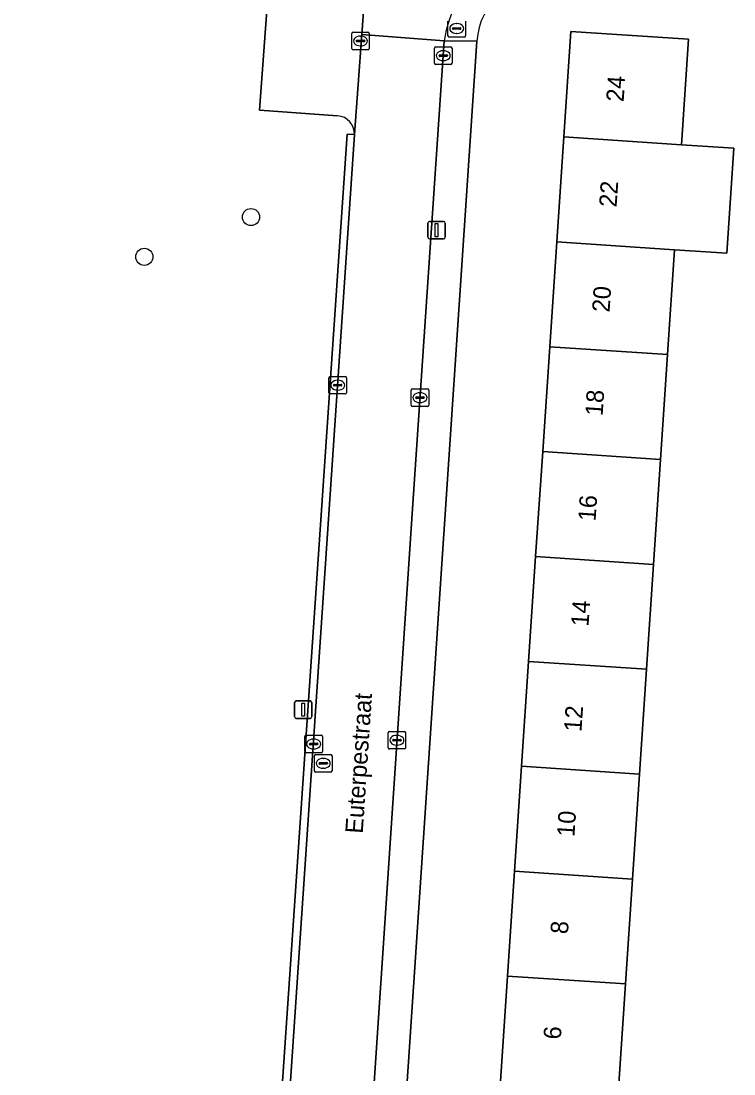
# Model space of a CAD drawing. Extents: x 161848 to 162726, y 385382 to 386521.
# Drawn here: x 161955.5 to 161996.3, y 386169.4 to 386229.5 of the extents above; entities that cross this region are included whole.
import ezdxf

# ---------------------------------------------------------------- set-up
doc = ezdxf.new("R2010")
doc.units = 0
for name, color, linetype in [('IMGEO_Boom', 7, 'Continuous'), ('IMGEO_Brandkraan', 7, 'Continuous'), ('IMGEO_Erf', 7, 'Continuous'), ('IMGEO_Groenvoorziening', 7, 'Continuous'), ('IMGEO_Kolk', 7, 'Continuous'), ('IMGEO_Lichtmast', 7, 'Continuous'), ('IMGEO_Openbare_ruimte_label', 7, 'Continuous'), ('IMGEO_Pand', 7, 'Continuous'), ('IMGEO_Pand_nummerreeks', 7, 'Continuous'), ('IMGEO_Parkeervlak_open', 7, 'Continuous'), ('IMGEO_Rijbaan_lokaal_open', 7, 'Continuous'), ('IMGEO_Rioolput', 7, 'Continuous'), ('IMGEO_Verkeerseiland_open', 7, 'Continuous'), ('IMGEO_Voetpad_open', 7, 'Continuous')]:
    doc.layers.add(name, color=color, linetype=linetype)

msp = doc.modelspace()

# ---------------------------------------------------------------- linework, layer by layer
at = {"layer": 'IMGEO_Boom'}
for centre in [(161968.672, 386218.342), (161962.577, 386216.067)]:
    msp.add_circle(centre, 0.489, dxfattribs=at)
at = {"layer": 'IMGEO_Brandkraan'}
for p, q in [((161979.933, 386228.689), (161979.933, 386229.541)), ((161980.421, 386229.395), (161980.446, 386229.395)), ((161980.934, 386229.541), (161980.934, 386228.689)), ((161980.86, 386228.615), (161980.008, 386228.615)), ((161980.192, 386229.109), (161980.192, 386229.121)), ((161980.63, 386229.072), (161980.232, 386229.072)), ((161980.235, 386229.158), (161980.633, 386229.158)), ((161980.444, 386228.835), (161980.419, 386228.835)), ((161980.676, 386229.121), (161980.676, 386229.109))]:
    msp.add_line(p, q, dxfattribs=at)
for points in [[(161979.933, 386228.689), (161979.933, 386229.541)], [(161980.934, 386229.541), (161980.934, 386228.689)], [(161980.86, 386228.615), (161980.008, 386228.615)]]:
    msp.add_lwpolyline(points, dxfattribs=at)
for centre, radius, start, end in [((161980.01, 386228.691), 0.0765, 181.55205, 268.44795), ((161980.01, 386228.691), 0.0765, 181.55205, 268.44795), ((161980.232, 386229.118), 0.0403, 85.87752, 175.75265), ((161980.229, 386229.108), 0.0366, 178.93798, 274.71019), ((161980.633, 386229.115), 0.043, 264.86636, 352.45326), ((161980.637, 386229.12), 0.0386, 1.73085, 96.63898), ((161980.858, 386228.691), 0.0765, 271.55205, 358.44795), ((161980.858, 386228.691), 0.0765, 271.55205, 358.44795)]:
    msp.add_arc(centre, radius, start, end, dxfattribs=at)
for centre, major_axis, ratio, start_param, end_param in [((161980.42, 386229.115), (-0.387, 0.002), 0.722429, 4.712389, 7.853982), ((161980.445, 386229.115), (-0.39, 0.002), 0.717154, 1.570796, 4.712389)]:
    msp.add_ellipse(centre, major_axis=major_axis, ratio=ratio, start_param=start_param, end_param=end_param, dxfattribs=at)
at = {"layer": 'IMGEO_Erf'}
for points in [[(161982.937, 386168.979), (161983.339, 386174.973), (161983.74, 386180.967), (161984.141, 386186.961), (161984.543, 386192.955), (161984.944, 386198.948), (161985.346, 386204.941), (161985.747, 386210.936), (161986.149, 386216.93), (161986.55, 386222.924), (161986.954, 386228.951), (161993.689, 386228.5), (161993.285, 386222.473), (161996.278, 386222.273), (161995.877, 386216.278), (161992.884, 386216.479), (161992.482, 386210.485), (161992.081, 386204.491), (161991.679, 386198.498), (161991.278, 386192.504), (161990.876, 386186.51), (161990.475, 386180.516), (161990.074, 386174.523), (161989.672, 386168.529)], [(161981.585, 386228.399), (161976.646, 386154.728)]]:
    msp.add_lwpolyline(points, dxfattribs=at)
msp.add_arc((161985.479, 386228.136), 3.903, 86.19164, 176.13527, dxfattribs=at)
at = {"layer": 'IMGEO_Groenvoorziening'}
for points in [[(161973.622, 386224.131), (161969.156, 386224.443), (161970.081, 386236.899), (161970.003, 386237.069), (161959.96, 386237.714), (161960.789, 386250), (161961.577, 386261.676), (161960.683, 386261.649), (161960.872, 386264.321), (161951.691, 386264.934), (161951.406, 386249.482), (161944.516, 386146.672), (161954.397, 386146.32), (161963.923, 386145.981), (161964.898, 386160.997), (161969.377, 386160.715)], [(161970.434, 386161.661), (161969.985, 386161.69), (161974.167, 386223.078)], [(161974.167, 386223.078), (161974.584, 386223.052)]]:
    msp.add_lwpolyline(points, dxfattribs=at)
msp.add_arc((161973.548, 386223.097), 1.037, 357.50919, 85.92905, dxfattribs=at)
at = {"layer": 'IMGEO_Kolk'}
for p, q in [((161974.433, 386227.979), (161974.433, 386228.831)), ((161974.508, 386228.905), (161975.36, 386228.905)), ((161974.921, 386228.685), (161974.946, 386228.685)), ((161975.434, 386228.831), (161975.434, 386227.979)), ((161974.692, 386228.399), (161974.692, 386228.411)), ((161975.13, 386228.362), (161974.732, 386228.362)), ((161974.735, 386228.448), (161975.133, 386228.448)), ((161974.944, 386228.125), (161974.919, 386228.125)), ((161975.176, 386228.411), (161975.176, 386228.399)), ((161979.239, 386228.062), (161980.091, 386228.062)), ((161975.36, 386227.905), (161974.508, 386227.905)), ((161979.164, 386227.136), (161979.164, 386227.988)), ((161979.423, 386227.556), (161979.423, 386227.568)), ((161979.861, 386227.519), (161979.463, 386227.519)), ((161979.466, 386227.605), (161979.864, 386227.605)), ((161979.652, 386227.842), (161979.677, 386227.842)), ((161979.907, 386227.568), (161979.907, 386227.556)), ((161980.165, 386227.988), (161980.165, 386227.136)), ((161980.091, 386227.062), (161979.239, 386227.062)), ((161979.675, 386227.282), (161979.65, 386227.282)), ((161973.129, 386208.308), (161973.129, 386209.16)), ((161973.204, 386209.234), (161974.056, 386209.234)), ((161973.388, 386208.728), (161973.388, 386208.74)), ((161973.431, 386208.777), (161973.829, 386208.777)), ((161973.617, 386209.014), (161973.642, 386209.014)), ((161973.872, 386208.74), (161973.872, 386208.728)), ((161974.13, 386209.16), (161974.13, 386208.308)), ((161974.056, 386208.234), (161973.204, 386208.234)), ((161973.826, 386208.691), (161973.428, 386208.691)), ((161973.64, 386208.454), (161973.615, 386208.454)), ((161977.832, 386207.599), (161977.832, 386208.451)), ((161977.907, 386208.525), (161978.759, 386208.525)), ((161978.32, 386208.305), (161978.345, 386208.305)), ((161978.833, 386208.451), (161978.833, 386207.599)), ((161978.091, 386208.019), (161978.091, 386208.031)), ((161978.529, 386207.982), (161978.131, 386207.982)), ((161978.134, 386208.068), (161978.532, 386208.068)), ((161978.343, 386207.745), (161978.318, 386207.745)), ((161978.575, 386208.031), (161978.575, 386208.019)), ((161978.759, 386207.525), (161977.907, 386207.525)), ((161976.588, 386188.949), (161977.44, 386188.949)), ((161971.755, 386187.807), (161971.755, 386188.659)), ((161971.83, 386188.733), (161972.682, 386188.733)), ((161972.243, 386188.513), (161972.268, 386188.513)), ((161972.756, 386188.659), (161972.756, 386187.807)), ((161976.513, 386188.023), (161976.513, 386188.875)), ((161976.772, 386188.443), (161976.772, 386188.455)), ((161977.21, 386188.406), (161976.812, 386188.406)), ((161976.815, 386188.492), (161977.213, 386188.492)), ((161977.001, 386188.729), (161977.026, 386188.729)), ((161977.256, 386188.455), (161977.256, 386188.443)), ((161977.514, 386188.875), (161977.514, 386188.023)), ((161972.682, 386187.733), (161971.83, 386187.733)), ((161972.014, 386188.227), (161972.014, 386188.239)), ((161972.452, 386188.19), (161972.054, 386188.19)), ((161972.057, 386188.276), (161972.455, 386188.276)), ((161972.266, 386187.953), (161972.241, 386187.953)), ((161972.498, 386188.239), (161972.498, 386188.227)), ((161977.44, 386187.949), (161976.588, 386187.949)), ((161977.024, 386188.169), (161976.999, 386188.169))]:
    msp.add_line(p, q, dxfattribs=at)
for points in [[(161974.433, 386227.979), (161974.433, 386228.831)], [(161974.508, 386228.905), (161975.36, 386228.905)], [(161975.434, 386228.831), (161975.434, 386227.979)], [(161979.239, 386228.062), (161980.091, 386228.062)], [(161975.36, 386227.905), (161974.508, 386227.905)], [(161979.164, 386227.136), (161979.164, 386227.988)], [(161980.165, 386227.988), (161980.165, 386227.136)], [(161980.091, 386227.062), (161979.239, 386227.062)], [(161973.129, 386208.308), (161973.129, 386209.16)], [(161973.204, 386209.234), (161974.056, 386209.234)], [(161974.13, 386209.16), (161974.13, 386208.308)], [(161974.056, 386208.234), (161973.204, 386208.234)], [(161977.832, 386207.599), (161977.832, 386208.451)], [(161977.907, 386208.525), (161978.759, 386208.525)], [(161978.833, 386208.451), (161978.833, 386207.599)], [(161978.759, 386207.525), (161977.907, 386207.525)], [(161976.588, 386188.949), (161977.44, 386188.949)], [(161971.755, 386187.807), (161971.755, 386188.659)], [(161971.83, 386188.733), (161972.682, 386188.733)], [(161972.756, 386188.659), (161972.756, 386187.807)], [(161976.513, 386188.023), (161976.513, 386188.875)], [(161977.514, 386188.875), (161977.514, 386188.023)], [(161972.682, 386187.733), (161971.83, 386187.733)], [(161977.44, 386187.949), (161976.588, 386187.949)]]:
    msp.add_lwpolyline(points, dxfattribs=at)
for centre, radius, start, end in [((161974.51, 386228.829), 0.0765, 91.55205, 178.44795), ((161974.51, 386228.829), 0.0765, 91.55205, 178.44795), ((161975.358, 386228.829), 0.0765, 1.55205, 88.44795), ((161975.358, 386228.829), 0.0765, 1.55205, 88.44795), ((161974.732, 386228.408), 0.0403, 85.87752, 175.75265), ((161974.729, 386228.398), 0.0366, 178.93798, 274.71019), ((161975.133, 386228.405), 0.043, 264.86636, 352.45326), ((161975.137, 386228.41), 0.0386, 1.73085, 96.63898), ((161979.241, 386227.986), 0.0765, 91.55205, 178.44795), ((161979.241, 386227.986), 0.0765, 91.55205, 178.44795), ((161980.089, 386227.986), 0.0765, 1.55205, 88.44795), ((161980.089, 386227.986), 0.0765, 1.55205, 88.44795), ((161974.51, 386227.981), 0.0765, 181.55205, 268.44795), ((161974.51, 386227.981), 0.0765, 181.55205, 268.44795), ((161975.358, 386227.981), 0.0765, 271.55205, 358.44795), ((161975.358, 386227.981), 0.0765, 271.55205, 358.44795), ((161979.463, 386227.565), 0.0403, 85.87752, 175.75265), ((161979.46, 386227.555), 0.0366, 178.93798, 274.71019), ((161979.864, 386227.562), 0.043, 264.86636, 352.45326), ((161979.868, 386227.567), 0.0386, 1.73085, 96.63898), ((161979.241, 386227.138), 0.0765, 181.55205, 268.44795), ((161979.241, 386227.138), 0.0765, 181.55205, 268.44795), ((161980.089, 386227.138), 0.0765, 271.55205, 358.44795), ((161980.089, 386227.138), 0.0765, 271.55205, 358.44795), ((161973.206, 386209.158), 0.0765, 91.55205, 178.44795), ((161973.206, 386209.158), 0.0765, 91.55205, 178.44795), ((161973.428, 386208.737), 0.0403, 85.87752, 175.75265), ((161973.833, 386208.739), 0.0386, 1.73085, 96.63898), ((161974.054, 386209.158), 0.0765, 1.55205, 88.44795), ((161974.054, 386209.158), 0.0765, 1.55205, 88.44795), ((161973.206, 386208.31), 0.0765, 181.55205, 268.44795), ((161973.206, 386208.31), 0.0765, 181.55205, 268.44795), ((161973.425, 386208.727), 0.0366, 178.93798, 274.71019), ((161973.829, 386208.734), 0.043, 264.86636, 352.45326), ((161974.054, 386208.31), 0.0765, 271.55205, 358.44795), ((161974.054, 386208.31), 0.0765, 271.55205, 358.44795), ((161977.909, 386208.449), 0.0765, 91.55205, 178.44795), ((161977.909, 386208.449), 0.0765, 91.55205, 178.44795), ((161978.757, 386208.449), 0.0765, 1.55205, 88.44795), ((161978.757, 386208.449), 0.0765, 1.55205, 88.44795), ((161977.909, 386207.601), 0.0765, 181.55205, 268.44795), ((161977.909, 386207.601), 0.0765, 181.55205, 268.44795), ((161978.131, 386208.028), 0.0403, 85.87752, 175.75265), ((161978.128, 386208.018), 0.0366, 178.93798, 274.71019), ((161978.532, 386208.025), 0.043, 264.86636, 352.45326), ((161978.536, 386208.03), 0.0386, 1.73085, 96.63898), ((161978.757, 386207.601), 0.0765, 271.55205, 358.44795), ((161978.757, 386207.601), 0.0765, 271.55205, 358.44795), ((161976.59, 386188.873), 0.0765, 91.55205, 178.44795), ((161976.59, 386188.873), 0.0765, 91.55205, 178.44795), ((161977.438, 386188.873), 0.0765, 1.55205, 88.44795), ((161977.438, 386188.873), 0.0765, 1.55205, 88.44795), ((161971.832, 386188.657), 0.0765, 91.55205, 178.44795), ((161971.832, 386188.657), 0.0765, 91.55205, 178.44795), ((161972.68, 386188.657), 0.0765, 1.55205, 88.44795), ((161972.68, 386188.657), 0.0765, 1.55205, 88.44795), ((161976.812, 386188.452), 0.0403, 85.87752, 175.75265), ((161976.809, 386188.442), 0.0366, 178.93798, 274.71019), ((161977.213, 386188.449), 0.043, 264.86636, 352.45326), ((161977.217, 386188.454), 0.0386, 1.73085, 96.63898), ((161971.832, 386187.809), 0.0765, 181.55205, 268.44795), ((161971.832, 386187.809), 0.0765, 181.55205, 268.44795), ((161972.054, 386188.236), 0.0403, 85.87752, 175.75265), ((161972.051, 386188.226), 0.0366, 178.93798, 274.71019), ((161972.455, 386188.233), 0.043, 264.86636, 352.45326), ((161972.459, 386188.238), 0.0386, 1.73085, 96.63898), ((161972.68, 386187.809), 0.0765, 271.55205, 358.44795), ((161972.68, 386187.809), 0.0765, 271.55205, 358.44795), ((161976.59, 386188.025), 0.0765, 181.55205, 268.44795), ((161976.59, 386188.025), 0.0765, 181.55205, 268.44795), ((161977.438, 386188.025), 0.0765, 271.55205, 358.44795), ((161977.438, 386188.025), 0.0765, 271.55205, 358.44795)]:
    msp.add_arc(centre, radius, start, end, dxfattribs=at)
for centre, major_axis, ratio, start_param, end_param in [((161974.92, 386228.405), (-0.387, 0.002), 0.722429, 4.712389, 7.853982), ((161974.945, 386228.405), (-0.39, 0.002), 0.717154, 1.570796, 4.712389), ((161979.651, 386227.562), (-0.387, 0.002), 0.722429, 4.712389, 7.853982), ((161979.676, 386227.562), (-0.39, 0.002), 0.717154, 1.570796, 4.712389), ((161973.616, 386208.734), (-0.387, 0.002), 0.722429, 4.712389, 7.853982), ((161973.641, 386208.734), (-0.39, 0.002), 0.717154, 1.570796, 4.712389), ((161978.319, 386208.025), (-0.387, 0.002), 0.722429, 4.712389, 7.853982), ((161978.344, 386208.025), (-0.39, 0.002), 0.717154, 1.570796, 4.712389), ((161972.242, 386188.233), (-0.387, 0.002), 0.722429, 4.712389, 7.853982), ((161972.267, 386188.233), (-0.39, 0.002), 0.717154, 1.570796, 4.712389), ((161977, 386188.449), (-0.387, 0.002), 0.722429, 4.712389, 7.853982), ((161977.025, 386188.449), (-0.39, 0.002), 0.717154, 1.570796, 4.712389)]:
    msp.add_ellipse(centre, major_axis=major_axis, ratio=ratio, start_param=start_param, end_param=end_param, dxfattribs=at)
at = {"layer": 'IMGEO_Lichtmast'}
for p, q in [((161978.783, 386217.195), (161978.783, 386217.995)), ((161978.783, 386217.995), (161978.783, 386217.195)), ((161978.883, 386218.095), (161979.673, 386218.095)), ((161979.673, 386218.095), (161978.883, 386218.095)), ((161979.773, 386217.995), (161979.773, 386217.195)), ((161979.773, 386217.195), (161979.773, 386217.995)), ((161979.673, 386217.095), (161978.883, 386217.095)), ((161978.883, 386217.095), (161979.673, 386217.095)), ((161971.261, 386190.698), (161972.051, 386190.698)), ((161972.051, 386190.698), (161971.261, 386190.698)), ((161971.161, 386189.798), (161971.161, 386190.598)), ((161971.161, 386190.598), (161971.161, 386189.798)), ((161972.151, 386190.598), (161972.151, 386189.798)), ((161972.151, 386189.798), (161972.151, 386190.598)), ((161972.051, 386189.698), (161971.261, 386189.698)), ((161971.261, 386189.698), (161972.051, 386189.698))]:
    msp.add_line(p, q, dxfattribs=at)
for points in [[(161979.203, 386217.97), (161979.353, 386217.97), (161979.353, 386217.22), (161979.203, 386217.22), (161979.203, 386217.97)], [(161971.581, 386190.573), (161971.731, 386190.573), (161971.731, 386189.823), (161971.581, 386189.823), (161971.581, 386190.573)]]:
    msp.add_lwpolyline(points, dxfattribs=at)
for centre, start, end in [((161978.883, 386217.995), 90, 180), ((161978.883, 386217.995), 90, 180), ((161979.673, 386217.995), 0, 90), ((161979.673, 386217.995), 360, 90), ((161978.883, 386217.195), 180, 270), ((161978.883, 386217.195), 180, 270), ((161979.673, 386217.195), 270, 0), ((161979.673, 386217.195), 270, 0), ((161971.261, 386190.598), 90, 180), ((161971.261, 386190.598), 90, 180), ((161972.051, 386190.598), 0, 90), ((161972.051, 386190.598), 360, 90), ((161971.261, 386189.798), 180, 270), ((161971.261, 386189.798), 180, 270), ((161972.051, 386189.798), 270, 0), ((161972.051, 386189.798), 270, 0)]:
    msp.add_arc(centre, 0.1, start, end, dxfattribs=at)
at = {"layer": 'IMGEO_Pand'}
for points in [[(161993.689, 386228.5), (161986.954, 386228.951), (161986.55, 386222.924), (161992.995, 386222.492), (161993.285, 386222.473)], [(161995.877, 386216.278), (161996.278, 386222.273), (161993.285, 386222.473), (161992.995, 386222.492), (161986.55, 386222.924), (161986.149, 386216.93), (161992.593, 386216.498), (161992.884, 386216.479)], [(161985.747, 386210.936), (161992.192, 386210.504), (161992.482, 386210.485), (161992.884, 386216.479), (161992.593, 386216.498), (161986.149, 386216.93)], [(161985.346, 386204.941), (161991.79, 386204.51), (161992.081, 386204.491), (161992.482, 386210.485), (161992.192, 386210.504), (161985.747, 386210.936)], [(161984.944, 386198.948), (161991.389, 386198.517), (161991.679, 386198.498), (161992.081, 386204.491), (161991.79, 386204.51), (161985.346, 386204.941)], [(161984.543, 386192.955), (161990.988, 386192.523), (161991.278, 386192.504), (161991.679, 386198.498), (161991.389, 386198.517), (161984.944, 386198.948)], [(161991.278, 386192.504), (161990.988, 386192.523), (161984.543, 386192.955), (161984.141, 386186.961), (161990.587, 386186.529), (161990.876, 386186.51)], [(161990.876, 386186.51), (161990.587, 386186.529), (161984.141, 386186.961), (161983.74, 386180.967), (161990.186, 386180.535), (161990.475, 386180.516)], [(161990.475, 386180.516), (161990.186, 386180.535), (161983.74, 386180.967), (161983.339, 386174.973), (161989.785, 386174.542), (161990.074, 386174.523)], [(161990.074, 386174.523), (161989.785, 386174.542), (161983.339, 386174.973), (161982.937, 386168.979), (161989.384, 386168.548), (161989.672, 386168.529)]]:
    msp.add_lwpolyline(points, close=True, dxfattribs=at)
at = {"layer": 'IMGEO_Parkeervlak_open'}
for points in [[(161974.584, 386223.052), (161975.001, 386228.781), (161975.635, 386237.495)], [(161974.536, 386236.6), (161970.081, 386236.899), (161969.156, 386224.443), (161973.622, 386224.131)]]:
    msp.add_lwpolyline(points, dxfattribs=at)
msp.add_arc((161973.548, 386223.097), 1.037, 357.50919, 85.92905, dxfattribs=at)
at = {"layer": 'IMGEO_Rijbaan_lokaal_open'}
msp.add_lwpolyline([(161985.74, 386239.152), (161984.256, 386239.27), (161975.804, 386239.853), (161975.635, 386237.495), (161975.001, 386228.781), (161979.722, 386228.416)], dxfattribs=at)
msp.add_lwpolyline([(161979.722, 386228.416), (161975.001, 386228.781), (161974.584, 386223.052), (161970.434, 386161.661), (161969.52, 386147.428), (161974.259, 386147.202), (161977.919, 386201.963)], close=True, dxfattribs=at)
msp.add_arc((161985.879, 386227.635), 6.206, 85.57219, 172.77397, dxfattribs=at)
at = {"layer": 'IMGEO_Rioolput'}
for p, q in [((161972.303, 386186.705), (161972.303, 386187.557)), ((161972.378, 386187.631), (161973.23, 386187.631)), ((161972.562, 386187.125), (161972.562, 386187.137)), ((161973, 386187.088), (161972.602, 386187.088)), ((161972.605, 386187.174), (161973.003, 386187.174)), ((161972.791, 386187.411), (161972.816, 386187.411)), ((161973.046, 386187.137), (161973.046, 386187.125)), ((161973.304, 386187.557), (161973.304, 386186.705)), ((161973.23, 386186.631), (161972.378, 386186.631)), ((161972.814, 386186.851), (161972.789, 386186.851))]:
    msp.add_line(p, q, dxfattribs=at)
for points in [[(161972.303, 386186.705), (161972.303, 386187.557)], [(161972.378, 386187.631), (161973.23, 386187.631)], [(161973.304, 386187.557), (161973.304, 386186.705)], [(161973.23, 386186.631), (161972.378, 386186.631)]]:
    msp.add_lwpolyline(points, dxfattribs=at)
for centre, radius, start, end in [((161972.38, 386187.555), 0.0765, 91.55205, 178.44795), ((161972.38, 386187.555), 0.0765, 91.55205, 178.44795), ((161972.602, 386187.134), 0.0403, 85.87752, 175.75265), ((161972.599, 386187.124), 0.0366, 178.93798, 274.71019), ((161973.003, 386187.131), 0.043, 264.86636, 352.45326), ((161973.007, 386187.136), 0.0386, 1.73085, 96.63898), ((161973.228, 386187.555), 0.0765, 1.55205, 88.44795), ((161973.228, 386187.555), 0.0765, 1.55205, 88.44795), ((161972.38, 386186.707), 0.0765, 181.55205, 268.44795), ((161972.38, 386186.707), 0.0765, 181.55205, 268.44795), ((161973.228, 386186.707), 0.0765, 271.55205, 358.44795), ((161973.228, 386186.707), 0.0765, 271.55205, 358.44795)]:
    msp.add_arc(centre, radius, start, end, dxfattribs=at)
for centre, major_axis, ratio, start_param, end_param in [((161972.79, 386187.131), (-0.387, 0.002), 0.722429, 4.712389, 7.853982), ((161972.815, 386187.131), (-0.39, 0.002), 0.717154, 1.570796, 4.712389)]:
    msp.add_ellipse(centre, major_axis=major_axis, ratio=ratio, start_param=start_param, end_param=end_param, dxfattribs=at)
at = {"layer": 'IMGEO_Verkeerseiland_open'}
msp.add_lwpolyline([(161974.167, 386223.078), (161969.985, 386161.69), (161970.434, 386161.661), (161974.584, 386223.052)], close=True, dxfattribs=at)
at = {"layer": 'IMGEO_Voetpad_open'}
for points in [[(161981.585, 386228.399), (161979.722, 386228.416), (161977.919, 386201.963), (161974.259, 386147.202), (161974.226, 386146.71)], [(161976.126, 386146.967), (161976.606, 386154.129), (161976.646, 386154.728), (161981.585, 386228.399)], [(161979.722, 386228.416), (161981.585, 386228.399)]]:
    msp.add_lwpolyline(points, dxfattribs=at)
for centre, radius, start, end in [((161985.879, 386227.635), 6.206, 85.57219, 172.77397), ((161985.479, 386228.136), 3.903, 86.19164, 176.13527)]:
    msp.add_arc(centre, radius, start, end, dxfattribs=at)

# ---------------------------------------------------------------- texts
at = {"layer": 'IMGEO_Openbare_ruimte_label'}
msp.add_text('Euterpestraat', height=1, rotation=86.15925, dxfattribs=at).set_placement((161975.057, 386183.094))
at = {"layer": 'IMGEO_Pand_nummerreeks'}
for s, p in [('24', (161989.97, 386224.901)), ('22', (161989.567, 386218.885)), ('20', (161989.165, 386212.878)), ('18', (161988.768, 386206.956)), ('16', (161988.365, 386200.94)), ('14', (161987.962, 386194.927)), ('12', (161987.56, 386188.911)), ('10', (161987.157, 386182.904)), ('8', (161986.785, 386177.351)), ('6', (161986.382, 386171.334))]:
    msp.add_text(s, height=1, rotation=86.16801, dxfattribs=at).set_placement(p)

doc.saveas('drawing.dxf')
